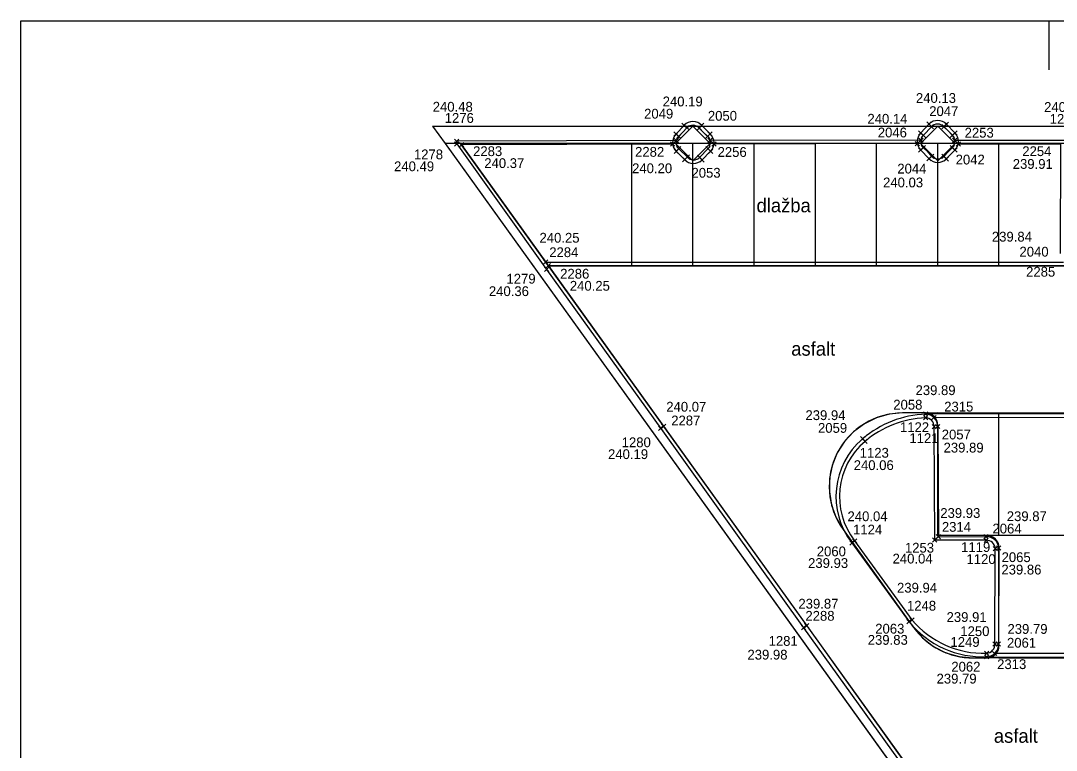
# Model space of a CAD drawing. Extents: x -264222 to -263676, y -1242344 to -1242060.
# Drawn here: x -264222.03 to -264179.73, y -1242216.25 to -1242186.47 of the extents above; entities that cross this region are included whole.
import ezdxf

# ---------------------------------------------------------------- set-up
doc = ezdxf.new("R2010")
doc.units = 0
for name, color, linetype in [('BODY_CISLO', 7, 'Continuous'), ('BODY_SYMBOL', 7, 'Continuous'), ('BODY_VYSKA', 7, 'Continuous'), ('KOORDINACNA_SITUACIA_DSP', 7, 'Continuous'), ('POPIS', 7, 'Continuous'), ('PROJEKT_DRS_OBRUBNIKY_KOMUNIKACIE', 7, 'Continuous'), ('PROJEKT_DRS_TDZ_VODOROVNE', 7, 'Continuous'), ('RAM_NA_TLAC_8xA4_1-200', 7, 'Continuous'), ('SO_20-3_OBRUBNIKY_DOLNA_HRANA', 7, 'Continuous'), ('SO_20-3_OBRUBNIKY_HORNA_HRANA', 7, 'Continuous')]:
    doc.layers.add(name, color=color, linetype=linetype)

msp = doc.modelspace()

# ---------------------------------------------------------------- linework, layer by layer
at = {"layer": 'BODY_SYMBOL'}
for p, q in [((-264195.016, -1242190.822), (-264194.84, -1242190.646)), ((-264194.84, -1242190.822), (-264195.016, -1242190.646)), ((-264194.9, -1242190.924), (-264194.724, -1242190.748)), ((-264194.724, -1242190.924), (-264194.9, -1242190.748)), ((-264194.4, -1242190.935), (-264194.224, -1242190.759)), ((-264194.224, -1242190.935), (-264194.4, -1242190.759)), ((-264194.299, -1242190.826), (-264194.123, -1242190.65)), ((-264194.123, -1242190.826), (-264194.299, -1242190.65)), ((-264185.01, -1242190.766), (-264184.834, -1242190.59)), ((-264184.834, -1242190.766), (-264185.01, -1242190.59)), ((-264184.912, -1242190.882), (-264184.736, -1242190.706)), ((-264184.736, -1242190.882), (-264184.912, -1242190.706)), ((-264184.408, -1242190.878), (-264184.232, -1242190.702)), ((-264184.232, -1242190.878), (-264184.408, -1242190.702)), ((-264184.303, -1242190.781), (-264184.127, -1242190.605)), ((-264184.127, -1242190.781), (-264184.303, -1242190.605)), ((-264195.349, -1242191.18), (-264195.173, -1242191.004)), ((-264195.173, -1242191.18), (-264195.349, -1242191.004)), ((-264195.235, -1242191.279), (-264195.059, -1242191.103)), ((-264195.059, -1242191.279), (-264195.235, -1242191.103)), ((-264194.059, -1242191.276), (-264193.883, -1242191.1)), ((-264193.883, -1242191.276), (-264194.059, -1242191.1)), ((-264193.956, -1242191.174), (-264193.78, -1242190.998)), ((-264193.78, -1242191.174), (-264193.956, -1242190.998)), ((-264185.359, -1242191.14), (-264185.183, -1242190.964)), ((-264185.183, -1242191.14), (-264185.359, -1242190.964)), ((-264185.243, -1242191.23), (-264185.067, -1242191.054)), ((-264185.067, -1242191.23), (-264185.243, -1242191.054)), ((-264184.059, -1242191.232), (-264183.883, -1242191.056)), ((-264183.883, -1242191.232), (-264184.059, -1242191.056)), ((-264183.952, -1242191.136), (-264183.776, -1242190.96)), ((-264183.776, -1242191.136), (-264183.952, -1242190.96)), ((-264204.314, -1242191.476), (-264204.138, -1242191.3)), ((-264204.138, -1242191.476), (-264204.314, -1242191.3)), ((-264204.308, -1242191.587), (-264204.132, -1242191.411)), ((-264204.132, -1242191.587), (-264204.308, -1242191.411)), ((-264204.11, -1242191.619), (-264203.934, -1242191.443)), ((-264203.934, -1242191.619), (-264204.11, -1242191.443)), ((-264195.489, -1242191.592), (-264195.313, -1242191.416)), ((-264195.313, -1242191.592), (-264195.489, -1242191.416)), ((-264195.334, -1242191.449), (-264195.158, -1242191.273)), ((-264195.158, -1242191.449), (-264195.334, -1242191.273)), ((-264195.238, -1242191.779), (-264195.062, -1242191.603)), ((-264195.062, -1242191.779), (-264195.238, -1242191.603)), ((-264194.043, -1242191.783), (-264193.867, -1242191.607)), ((-264193.867, -1242191.783), (-264194.043, -1242191.607)), ((-264193.957, -1242191.443), (-264193.781, -1242191.267)), ((-264193.781, -1242191.443), (-264193.957, -1242191.267)), ((-264193.797, -1242191.589), (-264193.621, -1242191.413)), ((-264193.621, -1242191.589), (-264193.797, -1242191.413)), ((-264185.49, -1242191.571), (-264185.314, -1242191.395)), ((-264185.314, -1242191.571), (-264185.49, -1242191.395)), ((-264185.346, -1242191.431), (-264185.17, -1242191.255)), ((-264185.17, -1242191.431), (-264185.346, -1242191.255)), ((-264185.24, -1242191.734), (-264185.064, -1242191.558)), ((-264185.064, -1242191.734), (-264185.24, -1242191.558)), ((-264184.059, -1242191.735), (-264183.883, -1242191.559)), ((-264183.883, -1242191.735), (-264184.059, -1242191.559)), ((-264183.961, -1242191.435), (-264183.785, -1242191.259)), ((-264183.785, -1242191.435), (-264183.961, -1242191.259)), ((-264183.82, -1242191.584), (-264183.644, -1242191.408)), ((-264183.644, -1242191.584), (-264183.82, -1242191.408)), ((-264195.338, -1242191.89), (-264195.162, -1242191.714)), ((-264195.162, -1242191.89), (-264195.338, -1242191.714)), ((-264194.884, -1242192.124), (-264194.708, -1242191.948)), ((-264194.708, -1242192.124), (-264194.884, -1242191.948)), ((-264194.377, -1242192.128), (-264194.201, -1242191.952)), ((-264194.201, -1242192.128), (-264194.377, -1242191.952)), ((-264193.937, -1242191.887), (-264193.761, -1242191.711)), ((-264193.761, -1242191.887), (-264193.937, -1242191.711)), ((-264185.356, -1242191.831), (-264185.18, -1242191.655)), ((-264185.18, -1242191.831), (-264185.356, -1242191.655)), ((-264185.008, -1242192.191), (-264184.832, -1242192.015)), ((-264184.832, -1242192.191), (-264185.008, -1242192.015)), ((-264184.9, -1242192.091), (-264184.724, -1242191.915)), ((-264184.724, -1242192.091), (-264184.9, -1242191.915)), ((-264184.404, -1242192.091), (-264184.228, -1242191.915)), ((-264184.228, -1242192.091), (-264184.404, -1242191.915)), ((-264184.309, -1242192.199), (-264184.133, -1242192.023)), ((-264184.133, -1242192.199), (-264184.309, -1242192.023)), ((-264183.956, -1242191.838), (-264183.78, -1242191.662)), ((-264183.78, -1242191.838), (-264183.956, -1242191.662)), ((-264194.992, -1242192.226), (-264194.816, -1242192.05)), ((-264194.816, -1242192.226), (-264194.992, -1242192.05)), ((-264194.287, -1242192.244), (-264194.111, -1242192.068)), ((-264194.111, -1242192.244), (-264194.287, -1242192.068)), ((-264200.669, -1242196.41), (-264200.493, -1242196.234)), ((-264200.493, -1242196.41), (-264200.669, -1242196.234)), ((-264200.638, -1242196.708), (-264200.462, -1242196.532)), ((-264200.462, -1242196.708), (-264200.638, -1242196.532)), ((-264200.558, -1242196.56), (-264200.382, -1242196.384)), ((-264200.382, -1242196.56), (-264200.558, -1242196.384)), ((-264185.154, -1242202.765), (-264184.978, -1242202.589)), ((-264184.978, -1242202.765), (-264185.154, -1242202.589)), ((-264185.146, -1242202.616), (-264184.97, -1242202.44)), ((-264184.97, -1242202.616), (-264185.146, -1242202.44)), ((-264184.813, -1242202.754), (-264184.637, -1242202.578)), ((-264184.637, -1242202.754), (-264184.813, -1242202.578)), ((-264195.972, -1242203.2), (-264195.796, -1242203.024)), ((-264195.796, -1242203.2), (-264195.972, -1242203.024)), ((-264195.853, -1242203.111), (-264195.677, -1242202.935)), ((-264195.677, -1242203.111), (-264195.853, -1242202.935)), ((-264184.803, -1242203.129), (-264184.627, -1242202.953)), ((-264184.627, -1242203.129), (-264184.803, -1242202.953)), ((-264184.657, -1242203.122), (-264184.481, -1242202.946)), ((-264184.481, -1242203.122), (-264184.657, -1242202.946)), ((-264187.723, -1242203.621), (-264187.547, -1242203.445)), ((-264187.547, -1242203.621), (-264187.723, -1242203.445)), ((-264187.625, -1242203.731), (-264187.449, -1242203.555)), ((-264187.449, -1242203.731), (-264187.625, -1242203.555)), ((-264188.053, -1242207.79), (-264187.877, -1242207.614)), ((-264187.877, -1242207.79), (-264188.053, -1242207.614)), ((-264184.78, -1242207.761), (-264184.604, -1242207.585)), ((-264184.604, -1242207.761), (-264184.78, -1242207.585)), ((-264184.63, -1242207.617), (-264184.454, -1242207.441)), ((-264184.454, -1242207.617), (-264184.63, -1242207.441)), ((-264182.683, -1242207.62), (-264182.507, -1242207.444)), ((-264182.507, -1242207.62), (-264182.683, -1242207.444)), ((-264182.679, -1242207.767), (-264182.503, -1242207.591)), ((-264182.503, -1242207.767), (-264182.679, -1242207.591)), ((-264188.166, -1242207.874), (-264187.99, -1242207.698)), ((-264187.99, -1242207.874), (-264188.166, -1242207.698)), ((-264182.307, -1242208.113), (-264182.131, -1242207.937)), ((-264182.131, -1242208.113), (-264182.307, -1242207.937)), ((-264182.164, -1242208.088), (-264181.988, -1242207.912)), ((-264181.988, -1242208.088), (-264182.164, -1242207.912)), ((-264185.825, -1242211.096), (-264185.649, -1242210.92)), ((-264185.649, -1242211.096), (-264185.825, -1242210.92)), ((-264185.709, -1242211.017), (-264185.533, -1242210.841)), ((-264185.533, -1242211.017), (-264185.709, -1242210.841)), ((-264190.134, -1242211.337), (-264189.958, -1242211.161)), ((-264189.958, -1242211.337), (-264190.134, -1242211.161)), ((-264190.011, -1242211.256), (-264189.835, -1242211.08)), ((-264189.835, -1242211.256), (-264190.011, -1242211.08)), ((-264182.324, -1242211.998), (-264182.148, -1242211.822)), ((-264182.148, -1242211.998), (-264182.324, -1242211.822)), ((-264182.177, -1242211.998), (-264182.001, -1242211.822)), ((-264182.001, -1242211.998), (-264182.177, -1242211.822)), ((-264182.664, -1242212.378), (-264182.488, -1242212.202)), ((-264182.488, -1242212.378), (-264182.664, -1242212.202)), ((-264182.335, -1242212.39), (-264182.159, -1242212.214)), ((-264182.159, -1242212.39), (-264182.335, -1242212.214)), ((-264182.654, -1242212.526), (-264182.478, -1242212.35)), ((-264182.478, -1242212.526), (-264182.654, -1242212.35))]:
    msp.add_line(p, q, dxfattribs=at)
at = {"layer": 'KOORDINACNA_SITUACIA_DSP'}
for p, q in [((-264205.202, -1242190.775), (-264179.193, -1242190.775)), ((-264205.202, -1242190.775), (-264204.694, -1242191.482)), ((-264178.679, -1242191.482), (-264204.694, -1242191.482)), ((-264204.694, -1242191.482), (-264122.859, -1242305.266)), ((-264179.568, -1242191.482), (-264204.078, -1242191.482)), ((-264204.078, -1242191.482), (-264122.243, -1242305.266)), ((-264185.068, -1242202.482), (-264186.002, -1242202.482)), ((-264188.438, -1242207.234), (-264185.561, -1242211.234)), ((-264182.068, -1242211.982), (-264182.068, -1242207.982)), ((-264183.125, -1242212.482), (-264182.568, -1242212.482))]:
    msp.add_line(p, q, dxfattribs=at)
for points in [[(-264194.568, -1242190.775), (-264193.861, -1242191.482), (-264194.568, -1242192.189), (-264195.275, -1242191.482)], [(-264184.568, -1242190.775), (-264183.861, -1242191.482), (-264184.568, -1242192.189), (-264185.275, -1242191.482)]]:
    msp.add_lwpolyline(points, close=True, dxfattribs=at)
for points in [[(-264204.694, -1242191.482), (-264137.78, -1242284.52), (-264125.581, -1242301.482)], [(-264193.861, -1242191.482), (-264193.861, -1242191.482), (-264194.568, -1242192.189), (-264195.275, -1242191.482)], [(-264183.861, -1242191.482), (-264183.861, -1242191.482), (-264184.568, -1242192.189), (-264185.275, -1242191.482)], [(-264182.568, -1242207.482), (-264184.568, -1242207.482), (-264184.568, -1242202.982)]]:
    msp.add_lwpolyline(points, dxfattribs=at)
for centre, radius, start, end in [((-264186.002, -1242205.482), 3, 90, 215.724), ((-264185.068, -1242202.982), 0.5, 0, 90), ((-264182.568, -1242207.982), 0.5, 0, 90), ((-264183.125, -1242209.482), 3, 215.724, 270), ((-264182.568, -1242211.982), 0.5, 270, 0)]:
    msp.add_arc(centre, radius, start, end, dxfattribs=at)
at = {"layer": 'PROJEKT_DRS_OBRUBNIKY_KOMUNIKACIE'}
for p, q in [((-264205.202, -1242190.775), (-264179.193, -1242190.775)), ((-264205.202, -1242190.775), (-264204.694, -1242191.482)), ((-264178.679, -1242191.482), (-264204.694, -1242191.482)), ((-264204.694, -1242191.482), (-264115.871, -1242314.982)), ((-264179.568, -1242191.482), (-264204.078, -1242191.482)), ((-264204.078, -1242191.482), (-264119.571, -1242308.982)), ((-264179.068, -1242196.482), (-264200.482, -1242196.482)), ((-264186.548, -1242202.532), (-264187.075, -1242202.681)), ((-264186.002, -1242202.482), (-264186.548, -1242202.532)), ((-264185.068, -1242202.482), (-264186.002, -1242202.482)), ((-264184.97, -1242202.492), (-264185.068, -1242202.482)), ((-264184.568, -1242202.482), (-264185.037, -1242202.483)), ((-264184.876, -1242202.52), (-264184.97, -1242202.492)), ((-264184.79, -1242202.567), (-264184.876, -1242202.52)), ((-264184.714, -1242202.629), (-264184.79, -1242202.567)), ((-264184.568, -1242202.482), (-264134.568, -1242202.482)), ((-264187.567, -1242202.922), (-264188.006, -1242203.25)), ((-264187.075, -1242202.681), (-264187.567, -1242202.922)), ((-264184.652, -1242202.704), (-264184.714, -1242202.629)), ((-264184.606, -1242202.791), (-264184.652, -1242202.704)), ((-264184.577, -1242202.885), (-264184.606, -1242202.791)), ((-264184.568, -1242202.982), (-264184.577, -1242202.885)), ((-264184.568, -1242207.482), (-264184.568, -1242202.982)), ((-264188.006, -1242203.25), (-264188.379, -1242203.651)), ((-264188.379, -1242203.651), (-264188.672, -1242204.114)), ((-264188.672, -1242204.114), (-264188.876, -1242204.622)), ((-264188.876, -1242204.622), (-264188.985, -1242205.159)), ((-264188.985, -1242205.159), (-264188.994, -1242205.707)), ((-264188.994, -1242205.707), (-264188.903, -1242206.247)), ((-264188.903, -1242206.247), (-264188.716, -1242206.762)), ((-264188.716, -1242206.762), (-264188.438, -1242207.234)), ((-264188.438, -1242207.234), (-264185.561, -1242211.234)), ((-264182.568, -1242207.482), (-264184.568, -1242207.482)), ((-264182.47, -1242207.492), (-264182.568, -1242207.482)), ((-264182.376, -1242207.52), (-264182.47, -1242207.492)), ((-264182.29, -1242207.567), (-264182.376, -1242207.52)), ((-264182.214, -1242207.629), (-264182.29, -1242207.567)), ((-264182.152, -1242207.704), (-264182.214, -1242207.629)), ((-264182.106, -1242207.791), (-264182.152, -1242207.704)), ((-264182.077, -1242207.885), (-264182.106, -1242207.791)), ((-264182.068, -1242207.982), (-264182.077, -1242207.885)), ((-264182.068, -1242211.982), (-264182.068, -1242207.982)), ((-264185.561, -1242211.234), (-264185.187, -1242211.661)), ((-264185.187, -1242211.661), (-264184.74, -1242212.011)), ((-264184.74, -1242212.011), (-264184.235, -1242212.269)), ((-264184.235, -1242212.269), (-264183.69, -1242212.429)), ((-264182.29, -1242212.398), (-264182.214, -1242212.336)), ((-264182.214, -1242212.336), (-264182.152, -1242212.26)), ((-264182.152, -1242212.26), (-264182.106, -1242212.174)), ((-264182.106, -1242212.174), (-264182.077, -1242212.08)), ((-264182.077, -1242212.08), (-264182.068, -1242211.982)), ((-264183.69, -1242212.429), (-264183.125, -1242212.482)), ((-264183.125, -1242212.482), (-264182.568, -1242212.482)), ((-264182.568, -1242212.482), (-264182.47, -1242212.473)), ((-264182.068, -1242212.482), (-264182.568, -1242212.482)), ((-264182.47, -1242212.473), (-264182.376, -1242212.444)), ((-264182.376, -1242212.444), (-264182.29, -1242212.398)), ((-264182.068, -1242212.482), (-264134.568, -1242212.482))]:
    msp.add_line(p, q, dxfattribs=at)
for points in [[(-264194.568, -1242190.775), (-264193.861, -1242191.482), (-264194.568, -1242192.189), (-264195.275, -1242191.482), (-264194.568, -1242190.775)], [(-264184.568, -1242190.775), (-264183.861, -1242191.482), (-264184.568, -1242192.189), (-264185.275, -1242191.482), (-264184.568, -1242190.775)], [(-264204.694, -1242191.482), (-264137.78, -1242284.52), (-264125.581, -1242301.482)], [(-264193.861, -1242191.482), (-264194.568, -1242192.189), (-264195.275, -1242191.482)], [(-264183.861, -1242191.482), (-264184.568, -1242192.189), (-264185.275, -1242191.482)]]:
    msp.add_lwpolyline(points, dxfattribs=at)
at = {"layer": 'PROJEKT_DRS_TDZ_VODOROVNE'}
for p, q in [((-264197.068, -1242196.482), (-264197.068, -1242191.482)), ((-264194.568, -1242196.482), (-264194.568, -1242191.482)), ((-264192.068, -1242196.482), (-264192.068, -1242191.482)), ((-264189.568, -1242196.482), (-264189.568, -1242191.482)), ((-264187.068, -1242196.482), (-264187.068, -1242191.482)), ((-264184.568, -1242196.482), (-264184.568, -1242191.482)), ((-264182.068, -1242196.482), (-264182.068, -1242191.482)), ((-264182.068, -1242207.482), (-264182.068, -1242202.482)), ((-264134.568, -1242207.482), (-264184.568, -1242207.482))]:
    msp.add_line(p, q, dxfattribs=at)
at = {"layer": 'RAM_NA_TLAC_8xA4_1-200'}
msp.add_line((-264180.03, -1242186.466), (-264180.03, -1242188.466), dxfattribs=at)
msp.add_lwpolyline([(-264222.03, -1242186.466), (-264054.03, -1242186.466), (-264054.03, -1242305.266), (-264222.03, -1242305.266)], close=True, dxfattribs=at)
at = {"layer": 'SO_20-3_OBRUBNIKY_DOLNA_HRANA'}
for p, q in [((-264194.928, -1242190.734), (-264195.261, -1242191.092)), ((-264193.868, -1242191.086), (-264194.211, -1242190.738)), ((-264184.922, -1242190.678), (-264185.271, -1242191.052)), ((-264183.864, -1242191.048), (-264184.215, -1242190.693)), ((-264185.402, -1242191.483), (-264193.709, -1242191.501)), ((-264195.25, -1242191.802), (-264194.904, -1242192.138)), ((-264194.199, -1242192.156), (-264193.849, -1242191.799)), ((-264185.268, -1242191.743), (-264184.92, -1242192.103)), ((-264184.221, -1242192.111), (-264183.868, -1242191.75)), ((-264188.078, -1242207.786), (-264185.737, -1242211.008)), ((-264182.076, -1242208), (-264182.089, -1242211.91))]:
    msp.add_line(p, q, dxfattribs=at)
for points in [[(-264195.401, -1242191.504), (-264204.022, -1242191.531), (-264200.581, -1242196.322), (-264179.427, -1242196.33)], [(-264183.732, -1242191.496), (-264179.548, -1242191.491), (-264179.573, -1242195.965)], [(-264179.08, -1242196.474), (-264200.47, -1242196.472), (-264195.765, -1242203.023), (-264189.923, -1242211.168), (-264184.11, -1242219.268), (-264178.281, -1242227.391), (-264171.252, -1242237.149), (-264164.83, -1242246.079), (-264158.406, -1242254.997), (-264151.981, -1242263.929), (-264145.549, -1242272.885), (-264139.496, -1242281.305), (-264132.148, -1242291.541), (-264125.165, -1242301.265), (-264124.808, -1242301.762)], [(-264134.11, -1242202.476), (-264147.578, -1242202.485), (-264162.578, -1242202.5), (-264185.058, -1242202.528)], [(-264184.725, -1242202.666), (-264162.575, -1242202.645), (-264147.576, -1242202.628), (-264134.442, -1242202.625)], [(-264184.569, -1242203.034), (-264184.542, -1242207.529), (-264182.595, -1242207.532)], [(-264134.418, -1242212.255), (-264152.594, -1242212.281), (-264171.607, -1242212.3), (-264182.247, -1242212.302)], [(-264182.566, -1242212.438), (-264171.604, -1242212.447), (-264152.604, -1242212.425), (-264134.055, -1242212.391)]]:
    msp.add_lwpolyline(points, dxfattribs=at)
for centre, major_axis, ratio, start_param, end_param in [((-264194.572, -1242191.076), (-0.302, -0.392), 0.999503, 2.980344, 4.603016), ((-264184.576, -1242191.049), (-0.062, 0.504), 0.999311, 5.368245, 6.911523), ((-264194.909, -1242191.442), (-0.16, -0.47), 0.999571, 4.2588, 5.852362), ((-264194.201, -1242191.452), (-0.291, 0.4), 0.99985, 3.305343, 4.915549), ((-264184.914, -1242191.396), (-0.272, -0.414), 0.999877, 4.527661, 6.069602), ((-264184.222, -1242191.397), (-0.08, 0.494), 0.999853, 3.767162, 5.323591), ((-264194.543, -1242191.796), (0.219, -0.447), 0.999918, 5.014728, 6.589616), ((-264184.566, -1242191.764), (0.181, 0.455), 0.998309, 2.7119, 4.30374), ((-264184.887, -1242206.762), (-4.234, -0.295), 0.998443, 4.683148, 5.347089), ((-264185.071, -1242203.03), (0.427, -0.264), 0.99985, 0.54496, 2.099101), ((-264185.637, -1242205.891), (-0.683, -3.015), 0.99972, 4.067533, 5.595179), ((-264182.568, -1242208.024), (-0.439, -0.224), 0.99977, 2.719752, 4.295242), ((-264182.713, -1242208.537), (3.856, -0.63), 0.999109, 3.989176, 4.911992), ((-264182.592, -1242211.935), (0.284, 0.417), 0.999521, 3.792299, 5.35903)]:
    msp.add_ellipse(centre, major_axis=major_axis, ratio=ratio, start_param=start_param, end_param=end_param, dxfattribs=at)
at = {"layer": 'SO_20-3_OBRUBNIKY_HORNA_HRANA'}
for p, q in [((-264195.147, -1242191.191), (-264194.812, -1242190.836)), ((-264194.312, -1242190.847), (-264193.971, -1242191.188)), ((-264185.155, -1242191.142), (-264184.824, -1242190.794)), ((-264184.32, -1242190.79), (-264183.971, -1242191.144)), ((-264195.246, -1242191.361), (-264204.226, -1242191.388)), ((-264185.258, -1242191.343), (-264193.869, -1242191.355)), ((-264183.873, -1242191.347), (-264179.397, -1242191.349)), ((-264194.796, -1242192.036), (-264195.15, -1242191.691)), ((-264193.955, -1242191.695), (-264194.289, -1242192.04)), ((-264184.812, -1242192.003), (-264185.152, -1242191.646)), ((-264183.971, -1242191.647), (-264184.316, -1242192.003)), ((-264187.965, -1242207.702), (-264185.621, -1242210.929)), ((-264182.236, -1242211.91), (-264182.219, -1242208.025))]:
    msp.add_line(p, q, dxfattribs=at)
for points in [[(-264204.226, -1242191.388), (-264204.22, -1242191.499), (-264200.55, -1242196.62), (-264195.884, -1242203.112), (-264190.046, -1242211.249), (-264184.226, -1242219.352), (-264178.398, -1242227.475), (-264171.378, -1242237.231), (-264164.951, -1242246.159), (-264158.525, -1242255.075), (-264152.106, -1242264.005), (-264145.671, -1242272.964), (-264139.631, -1242281.361), (-264132.272, -1242291.613), (-264125.285, -1242301.347), (-264124.926, -1242301.846)], [(-264182.591, -1242207.679), (-264184.692, -1242207.673), (-264184.715, -1242203.041)]]:
    msp.add_lwpolyline(points, dxfattribs=at)
for centre, major_axis, ratio, start_param, end_param in [((-264194.567, -1242191.078), (-0.319, -0.131), 0.998496, 3.487153, 5.112124), ((-264184.57, -1242191.042), (-0.203, -0.291), 0.998438, 2.968669, 4.547434), ((-264194.91, -1242191.442), (-0.237, 0.251), 0.999996, 0, 1.618948), ((-264194.211, -1242191.449), (-0.011, 0.355), 0.997731, 3.917722, 5.507056), ((-264184.913, -1242191.392), (-0.054, -0.344), 0.998126, 4.0675, 5.682955), ((-264184.233, -1242191.396), (0.016, 0.363), 0.999012, 3.992412, 5.521854), ((-264194.541, -1242191.795), (0.333, -0.113), 0.999031, 4.225387, 5.83739), ((-264184.564, -1242191.756), (0.234, -0.26), 0.998811, 4.76298, 6.339302), ((-264184.877, -1242206.791), (-4.107, -0.417), 0.997731, 4.657169, 5.311656), ((-264185.075, -1242203.037), (0.314, -0.175), 0.999168, 0.496598, 2.054568), ((-264185.632, -1242205.896), (-0.655, -2.878), 0.999692, 4.067639, 5.59479), ((-264182.573, -1242208.032), (-0.354, 0.001), 0.999491, 3.166138, 4.767755), ((-264182.698, -1242208.48), (3.746, -0.729), 0.998924, 4.031861, 4.936406), ((-264182.59, -1242211.935), (0.264, 0.238), 0.99932, 4.018089, 5.61991)]:
    msp.add_ellipse(centre, major_axis=major_axis, ratio=ratio, start_param=start_param, end_param=end_param, dxfattribs=at)

# ---------------------------------------------------------------- texts
at = {"layer": 'BODY_CISLO'}
for s, p in [('1276', (-264204.709, -1242190.637)), ('2049', (-264196.564, -1242190.463)), ('2050', (-264193.959, -1242190.549)), ('2047', (-264184.917, -1242190.358)), ('1255', (-264179.995, -1242190.676)), ('2046', (-264187.018, -1242191.23)), ('2253', (-264183.47, -1242191.238)), ('2283', (-264203.55, -1242191.993)), ('2282', (-264196.933, -1242192.02)), ('2254', (-264181.116, -1242191.993)), ('1278', (-264205.967, -1242192.124)), ('2256', (-264193.562, -1242192.026)), ('2042', (-264183.837, -1242192.335)), ('2044', (-264186.22, -1242192.705)), ('2053', (-264194.629, -1242192.875)), ('2284', (-264200.439, -1242196.118)), ('2040', (-264181.23, -1242196.097)), ('2286', (-264199.993, -1242196.997)), ('2285', (-264180.959, -1242196.916)), ('1279', (-264202.186, -1242197.2)), ('2058', (-264186.385, -1242202.343)), ('2315', (-264184.305, -1242202.422)), ('2287', (-264195.456, -1242202.989)), ('2059', (-264189.46, -1242203.292)), ('1122', (-264186.112, -1242203.262)), ('1121', (-264185.727, -1242203.708)), ('2057', (-264184.406, -1242203.561)), ('1280', (-264197.479, -1242203.88)), ('1123', (-264187.757, -1242204.308)), ('1124', (-264188.028, -1242207.441)), ('2314', (-264184.4, -1242207.332)), ('2064', (-264182.333, -1242207.401)), ('2060', (-264189.51, -1242208.333)), ('1253', (-264185.909, -1242208.184)), ('1119', (-264183.614, -1242208.157)), ('1120', (-264183.394, -1242208.648)), ('2065', (-264181.961, -1242208.57)), ('1248', (-264185.826, -1242210.552)), ('2288', (-264189.975, -1242210.964)), ('2063', (-264187.122, -1242211.49)), ('1250', (-264183.647, -1242211.591)), ('1281', (-264191.478, -1242211.988)), ('1249', (-264184.05, -1242212.032)), ('2061', (-264181.74, -1242212.064)), ('2062', (-264184.014, -1242213.041)), ('2313', (-264182.142, -1242212.938))]:
    msp.add_text(s, height=0.4, dxfattribs=at).set_placement(p)
at = {"layer": 'BODY_VYSKA'}
for s, p in [('240.13', (-264185.46, -1242189.822)), ('240.48', (-264205.199, -1242190.179)), ('240.19', (-264195.806, -1242189.963)), ('240.03', (-264180.223, -1242190.189)), ('240.14', (-264187.442, -1242190.67)), ('240.49', (-264206.778, -1242192.611)), ('240.37', (-264203.094, -1242192.481)), ('240.20', (-264197.055, -1242192.691)), ('239.91', (-264181.505, -1242192.514)), ('240.03', (-264186.802, -1242193.27)), ('240.25', (-264200.837, -1242195.528)), ('239.84', (-264182.357, -1242195.484)), ('240.25', (-264199.598, -1242197.49)), ('240.36', (-264202.905, -1242197.709)), ('239.89', (-264185.476, -1242201.751)), ('240.07', (-264195.659, -1242202.427)), ('239.94', (-264189.973, -1242202.771)), ('239.89', (-264184.331, -1242204.096)), ('240.19', (-264198.037, -1242204.363)), ('240.06', (-264188.002, -1242204.812)), ('239.93', (-264184.465, -1242206.767)), ('240.04', (-264188.255, -1242206.9)), ('239.87', (-264181.749, -1242206.897)), ('239.93', (-264189.865, -1242208.81)), ('240.04', (-264186.414, -1242208.628)), ('239.86', (-264181.969, -1242209.076)), ('239.94', (-264186.232, -1242209.817)), ('239.87', (-264190.261, -1242210.47)), ('239.91', (-264184.208, -1242211.015)), ('239.79', (-264181.72, -1242211.499)), ('239.83', (-264187.428, -1242211.946)), ('239.98', (-264192.342, -1242212.55)), ('239.79', (-264184.617, -1242213.529))]:
    msp.add_text(s, height=0.4, dxfattribs=at).set_placement(p)
at = {"layer": 'POPIS'}
msp.add_text('dlažba', height=0.5625, rotation=360, dxfattribs=at).set_placement((-264191.972, -1242194.289))
for p in [(-264190.555, -1242200.143), (-264182.277, -1242215.947)]:
    msp.add_text('asfalt', height=0.5625, dxfattribs=at).set_placement(p)

doc.saveas('drawing.dxf')
